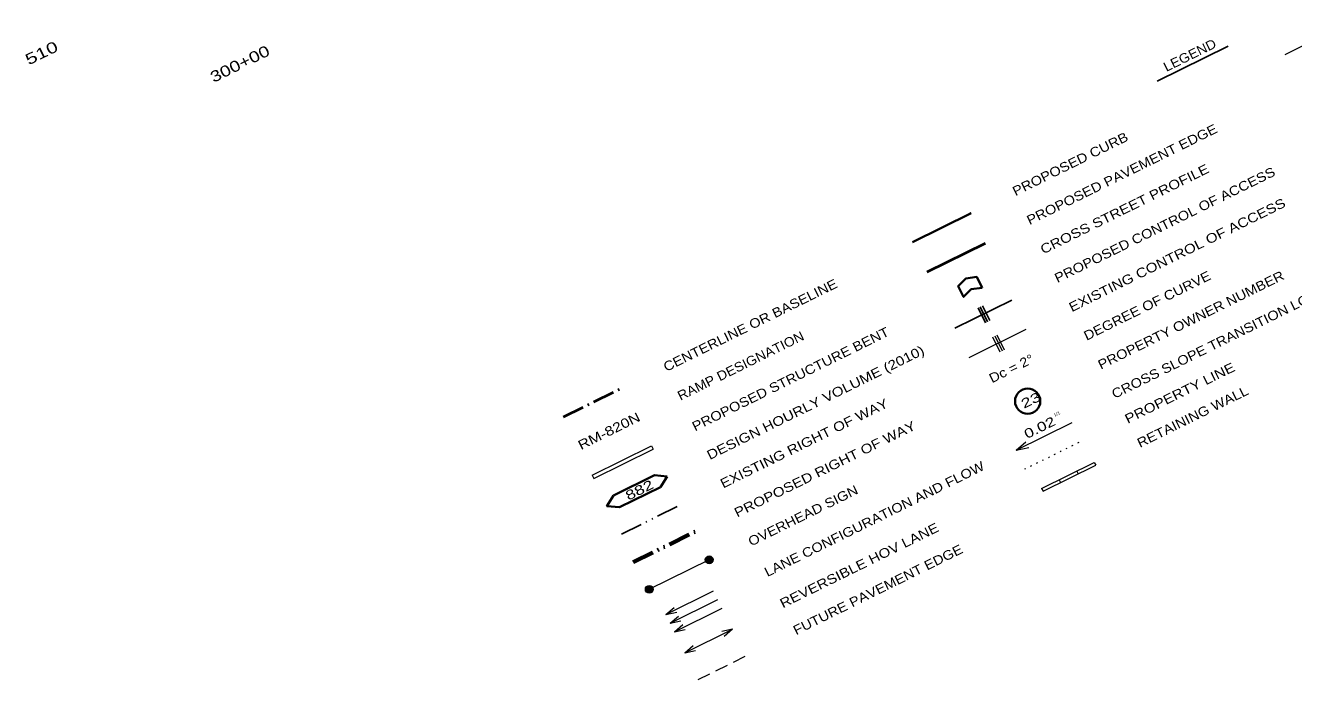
# Model space of a CAD drawing. Extents: x 2356431 to 2371438, y 6972864 to 6982525.
# Drawn here: x 2358861 to 2360481, y 6972864 to 6973699 of the extents above; entities that cross this region are included whole.
import ezdxf
from ezdxf.enums import TextEntityAlignment as Align

# ---------------------------------------------------------------- set-up
doc = ezdxf.new("R2010")
doc.units = 0
doc.header["$LTSCALE"] = 5.6
for name, pattern in [('DASH_DOUBLE_DOT', [9.2, 5, -1.2, 0.3, -1.2, 0.3, -1.2]), ('DOT_DASHED', [7.7, 5, -1.2, 0.3, -1.2]), ('DOTTED', [1.5, 0.3, -1.2]), ('MEDIUM_DASHED', [4.5, 3, -1.5])]:
    doc.linetypes.add(name, pattern=pattern)
doc.layers.add('3', color=7, linetype='Continuous', lineweight=13)
doc.layers.add('53', color=7, linetype='Continuous', lineweight=13)

msp = doc.modelspace()

# ---------------------------------------------------------------- hatches: boundary and pattern name
at = {"layer": '3'}
for points in [[(2359738.979, 6973019.177, 1), (2359730.011, 6973014.751, 1)], [(2359662.453, 6972981.494, 1), (2359653.485, 6972977.068, 1)]]:
    msp.add_hatch(color=256, dxfattribs=at).paths.add_polyline_path(points)

# ---------------------------------------------------------------- linework, layer by layer
for p, q in [((2360470.068, 6973662.181), (2360544.986, 6973699.156)), ((2359994.071, 6973423.478), (2360068.987, 6973460.452)), ((2359994.735, 6973422.133), (2360069.651, 6973459.107)), ((2360068.298, 6973460.111), (2360067.616, 6973459.775)), ((2360066.475, 6973275.369), (2360139.321, 6973311.321)), ((2360096.428, 6973301.382), (2360105.798, 6973282.398)), ((2360099.118, 6973302.709), (2360108.488, 6973283.726)), ((2360101.809, 6973304.038), (2360111.178, 6973285.053)), ((2360126.453, 6973156.759), (2360198.142, 6973192.14)), ((2359585.151, 6973124.985), (2359660.75, 6973162.296)), ((2359587.187, 6973120.86), (2359662.786, 6973158.171)), ((2359660.75, 6973162.296), (2359662.786, 6973158.171)), ((2360126.453, 6973156.759), (2360139.039, 6973167.544)), ((2360126.453, 6973156.759), (2360142.668, 6973160.19)), ((2360159.103, 6973108.116), (2360226.347, 6973141.334)), ((2360226.353, 6973141.32), (2360228.131, 6973137.723)), ((2359585.151, 6973124.985), (2359587.187, 6973120.86)), ((2360160.877, 6973104.52), (2360228.122, 6973137.736)), ((2360203.94, 6973130.247), (2360205.714, 6973126.651)), ((2360159.105, 6973108.104), (2360160.882, 6973104.509)), ((2360181.522, 6973119.176), (2360183.298, 6973115.581)), ((2359734.494, 6973016.962), (2359657.515, 6972978.971)), ((2359679.228, 6972947.113), (2359740.163, 6972977.186)), ((2359684.682, 6972936.063), (2359745.617, 6972966.136)), ((2359679.228, 6972947.113), (2359689.929, 6972956.275)), ((2359679.228, 6972947.113), (2359693.01, 6972950.033)), ((2359684.682, 6972936.063), (2359695.381, 6972945.226)), ((2359690.135, 6972925.016), (2359751.07, 6972955.089)), ((2359684.682, 6972936.063), (2359698.463, 6972938.984)), ((2359690.135, 6972925.016), (2359700.835, 6972934.177)), ((2359690.135, 6972925.016), (2359703.915, 6972927.936)), ((2359764.229, 6972928.426), (2359753.529, 6972919.264)), ((2359703.294, 6972898.352), (2359713.995, 6972907.514)), ((2359703.294, 6972898.352), (2359717.075, 6972901.273))]:
    msp.add_line(p, q, dxfattribs=at)
at = {"layer": '3', "lineweight": 25}
for p, q in [((2360306.659, 6973628.02), (2360397.133, 6973672.673)), ((2360048.12, 6973312.561), (2360120.966, 6973348.512)), ((2360078.073, 6973338.573), (2360087.443, 6973319.59)), ((2360080.764, 6973339.901), (2360090.133, 6973320.917)), ((2360083.454, 6973341.229), (2360092.823, 6973322.244))]:
    msp.add_line(p, q, dxfattribs=at)
at = {"layer": '3', "lineweight": 40}
msp.add_line((2360086.851, 6973420.801), (2360012.625, 6973384.168), dxfattribs=at)
at = {"layer": '3', "linetype": 'DOT_DASHED', "lineweight": 40}
msp.add_line((2359548.551, 6973199.415), (2359624.212, 6973236.756), dxfattribs=at)
at = {"layer": '3', "linetype": 'DOTTED'}
msp.add_line((2360137.493, 6973132.877), (2360212.409, 6973169.85), dxfattribs=at)
at = {"layer": '3', "lineweight": 35}
for p, q in [((2359672.111, 6973109.812), (2359680.79, 6973123.429)), ((2359619.865, 6973084.027), (2359672.111, 6973109.812))]:
    msp.add_line(p, q, dxfattribs=at)
at = {"layer": '3', "linetype": 'DASH_DOUBLE_DOT', "lineweight": 25}
msp.add_line((2359622.383, 6973049.816), (2359698.044, 6973087.157), dxfattribs=at)
at = {"layer": '3', "linetype": 'DASH_DOUBLE_DOT', "lineweight": 70}
msp.add_line((2359637.542, 6973013.905), (2359719.194, 6973054.203), dxfattribs=at)
at = {"layer": '3', "linetype": 'MEDIUM_DASHED'}
msp.add_line((2359720.24, 6972864.016), (2359781.175, 6972894.09), dxfattribs=at)
at = {"layer": '3', "lineweight": 35}
msp.add_lwpolyline([(2360083.002, 6973364.29), (2360069.183, 6973362.531), (2360059.388, 6973352.636), (2360052.634, 6973366.32), (2360062.429, 6973376.217), (2360076.248, 6973377.974)], close=True, dxfattribs=at)
for points in [[(2359612.398, 6973099.154), (2359664.644, 6973124.939), (2359680.79, 6973123.429)], [(2359612.398, 6973099.154), (2359603.81, 6973085.437), (2359619.865, 6973084.027)]]:
    msp.add_lwpolyline(points, dxfattribs=at)
at = {"layer": '3'}
msp.add_lwpolyline([(2359703.294, 6972898.352), (2359764.229, 6972928.426), (2359750.449, 6972925.505)], dxfattribs=at)
at = {"layer": '3', "lineweight": 35}
msp.add_circle((2360141.215, 6973219.454), 16.098, dxfattribs=at)
at = {"layer": '3'}
for centre in [(2359734.495, 6973016.964), (2359657.969, 6972979.281)]:
    msp.add_circle(centre, 5, dxfattribs=at)

# ---------------------------------------------------------------- texts
for s, height, width, p in [('LEGEND', 12, 1.1, (2360318.409, 6973639.663)), ('PROPOSED CURB', 12, 1.15, (2360125.607, 6973481.036)), ('PROPOSED PAVEMENT EDGE', 12, 1.15, (2360143.762, 6973444.115)), ('CROSS STREET PROFILE', 12, 1.2, (2360161.167, 6973406.815)), ('PROPOSED CONTROL OF ACCESS', 12, 1.15, (2360179.228, 6973370.219)), ('EXISTING CONTROL OF ACCESS', 12, 1.2, (2360197.583, 6973333.027)), ('DEGREE OF CURVE', 12, 1.15, (2360216.545, 6973296.506)), ('PROPERTY OWNER NUMBER', 12, 1.15, (2360234.757, 6973259.604)), ('CROSS SLOPE TRANSITION LOCATIONS', 12, 1.15, (2360252.211, 6973222.338)), ('CENTERLINE OR BASELINE', 12, 1.15, (2359679.721, 6973256.769)), ('RAMP DESIGNATION', 12, 1.1, (2359697.827, 6973219.946)), ('PROPOSED STRUCTURE BENT', 12, 1.15, (2359716.429, 6973180.876)), ('DESIGN HOURLY VOLUME (2010)', 12, 1.2, (2359735.244, 6973144.271)), ('Dc = 2°', 12, 1.15, (2360095.652, 6973242.216)), ('PROPERTY LINE', 12, 1.2, (2360269.029, 6973190.434)), ('RETAINING WALL', 12, 1.15, (2360284.727, 6973159.738)), ('EXISTING RIGHT OF WAY', 12, 1.2, (2359752.385, 6973107.888)), ('23', 12, 1.45, (2360136.356, 6973209.589)), ('RM-820N', 12, 1.25, (2359570.729, 6973156.985)), ('1/1', 4.18, 1.1, (2360175.664, 6973199.448)), ('PROPOSED RIGHT OF WAY', 12, 1.2, (2359770.271, 6973070.835)), ('0.02', 12, 1.35, (2360140.351, 6973171.079)), ('LANE CONFIGURATION AND FLOW', 12, 1.15, (2359808.793, 6972994.952)), ('882', 12, 1.4, (2359631.219, 6973092.385)), ('OVERHEAD SIGN', 12, 1.15, (2359788.066, 6973033.948)), ('REVERSIBLE HOV LANE', 12, 1.2, (2359828.515, 6972954.99)), ('FUTURE PAVEMENT EDGE', 12, 1.15, (2359845.461, 6972920.654))]:
    msp.add_text(s, height=height, rotation=26.268, dxfattribs=dict(at, width=width)).set_placement(p)
at = {"layer": '53', "width": 1.4}
msp.add_text('  510', height=14, rotation=26.268, dxfattribs=at).set_placement((2358904.623, 6973667.344), align=Align.RIGHT)
at = {"layer": '53', "width": 1.3}
msp.add_text('300+00', height=14, rotation=26.268, dxfattribs=at).set_placement((2359138.227, 6973643.766), align=Align.CENTER)

doc.saveas('drawing.dxf')
